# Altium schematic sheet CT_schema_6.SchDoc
size 296 x 198 mm
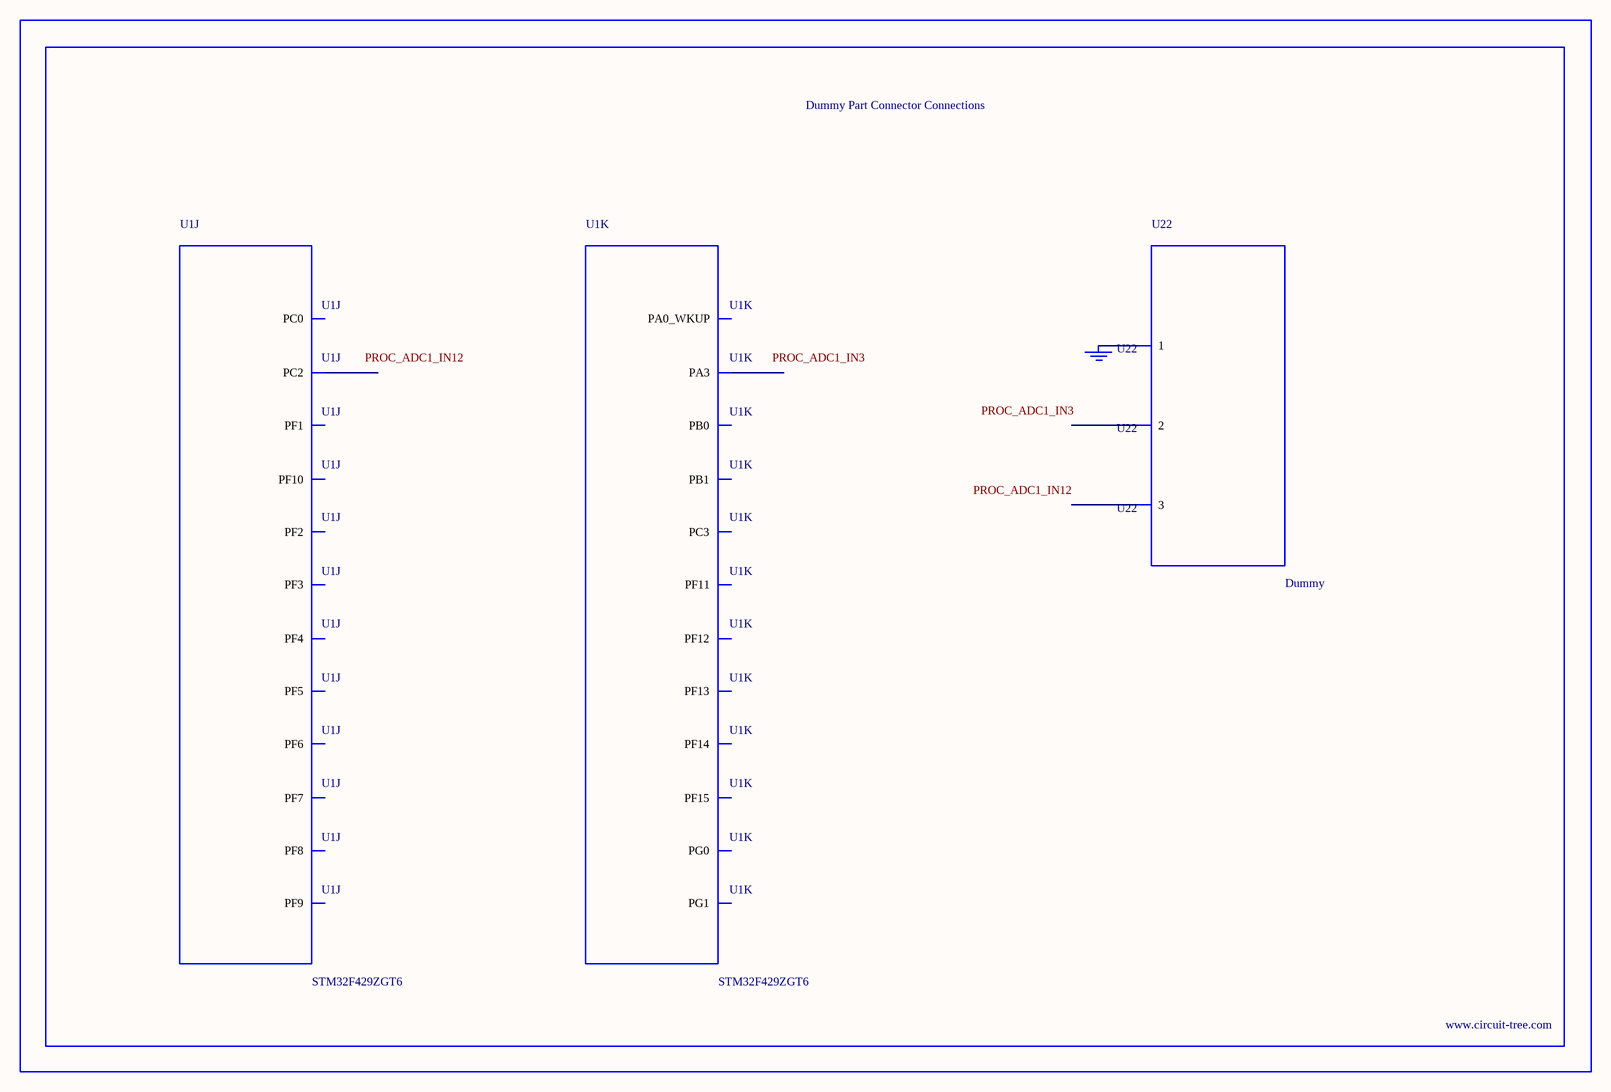
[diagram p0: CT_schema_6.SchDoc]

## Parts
BORDER5  (no value)
GND_INSTANCE_5_0  (no value)
U1  STM32F429ZGT6  [LQFP144]  (parts J,K of 11)
U22  Dummy  [DUMMY_PACKAGE_256]

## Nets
NetGND_INSTANCE_5_0_0: GND_INSTANCE_5_0.0(GND) U22.1

Not connected (* = marked no-connect by the designer): U1 11(PF1) 12(PF2) 13(PF3) 14(PF4) 15(PF5) 18(PF6) 19(PF7) 20(PF8) 21(PF9) 22(PF10) 26(PC0) 28(PC2) 29(PC3) 34(PA0_WKUP) 37(PA3) 46(PB0) 47(PB1) 49(PF11) 50(PF12) 53(PF13) 54(PF14) 55(PF15) 56(PG0) 57(PG1); U22 2 3

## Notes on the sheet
- Labels drawn without touching a wire or pin: PROC_ADC1_IN3, PROC_ADC1_IN12

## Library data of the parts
BORDER5 = BORDER_PAGE5
GND_INSTANCE_5_0 = GND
